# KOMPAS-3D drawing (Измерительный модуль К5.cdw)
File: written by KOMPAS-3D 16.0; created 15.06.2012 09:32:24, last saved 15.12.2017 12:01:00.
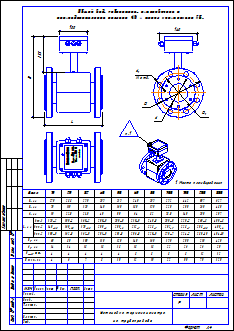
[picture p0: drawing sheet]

Sheet 1: A4, portrait

Title block, sheet 1: name: г. Москва, ул. Нежинская, д. 14, к.8 (кв. 1 и кв. 2); sheets: 31; sheet format: A4; stored path: W:\Users\chesnokov\Desktop\Новая папка\5 тр LTKR.cdw; cell 320: Р

Views: Вид 2, Вид 3, Вид 4, Вид 5
Referenced files in C:\Program Files (x86)\ASCON\KOMPAS-3D V16\Sys\: SPDS.lcs, EngSys.lcs, GRAPHIC.LHS
Referenced files: graphic.tdp
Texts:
  МО, Клинский район, д. Решетниково, ул. Центральная, д.14
  GOST Common
  Normal
  List Paragraph
  heading 3
  для схемы
  txt
  краны
  Фоновая заливка
  Т0-элементы
  N отв.
  Сделано в России
  Тmax= 150 C
  ИНТЕЛПРИБОР
  Общий вид, габаритные, установочные и
  присоединительные размеры ИМ с типом конструкции К5.
  Ду,мм
  Н, мм
  D, мм
  d, мм
  вар.1
  L, мм
  вар.2
  вар.3
  Масса, кг
  1. Место пломбирования
  Размеры, параметризация
  сит. план
  подача ГВС
  обратка ГВС
  хвс
  обратка
  POLYLINE_STYLE_0.25_RGB_0_0_0
  стены
  Основная (не является границей для штриховки)
  POLYLINE_STYLE_0.18_RGB_0_0_0
  ХВС
  зеленая
  Красная тонкая
  арматура
  Подача
  Скрытая линия
  Ось Z
  Ось Y
  Ось X
  Образующая трубопровода (проектируемого)
  Трубопровод толщиной 0.6мм (одна линия)
  Трубопровод толщиной 1.2мм (одна линия)
  Трубопровод толщиной 1.0мм (одна линия)
  Трубопровод толщиной 0.8мм (одна линия)
  Трубопровод существующий (одна линия)
  Трубопровод невидимый (одна линия)
  Трубопровод демонтируемый (одна линия)
  Осевая трубопровода
  Осевая трубопровода (демонтируемого)
  Образующая трубопровода (существующего)
  Образующая трубопровода (невидимого)
  Изолированный трубопровод проектируемый (одна линия)
  Изолированный трубопровод существующий (одна линия)
  Образующая изоляции
  Изоляция
  Изолированный трубопровод невидимый (одна линия)
  Штрих пвс 075
  штрих пвс 2,5
  существующее оборудование
  Существующее оборудование
  K5LT_BASIC_RGB_0_0_255_THICK_0.53
  POLYLINE_STYLE_1.51_RGB_0_0_255
  POLYLINE_STYLE_0.50_RGB_128_128_128
  K5LT_AXLED_RGB_255_128_0_SC_1_THICK_0.18
  ACAD_ISO04W100_RGB_0_0_0_SC_1_THICK_0.18
  тонкая черная
  пломбировка
  Провода
  синий штрих
  Стили документа
  G2co
  расход вторичной воды объемный
  расход вторичной воды объемный при 70гр
  Gco
  расход теплоносителя массовый
  расход теплоносит объемн подающ
  расход теплоносит объемн обр
  Лапир
  Ghvs
  Im1
  Im2
  Im3
  Im4
  Im5
  Khvs
  норматив ХВС
  число подъездов
  число этажей
  Nkv
  число квартир
  тепловая нагрузка на отопление
  сумма Q
  Qgvs
  тепловая нагрузка ГВС
  тепловая нагрузка на циркуляцию ГВС
  иммитовставка или под манометр
  ro1
  ro2
  ro3
  ro4
  верх предел темп граф
  нижн предел темп граф
  темп подачи ГВС
  темп обр ГВС
  темр хол воды
  vzdh
  Kchn
  Ktp
  Knp
  beta
  tnv
  Vклап
  KLP
  RPD
  RDS
  PUMP
  ro5
  Переход К-76 x 3-38 x 2-09Г2С ГОСТ 17378-2001
  Переход ГОСТ 17378-2001
  Переход
  ГОСТ
  Сталь 09Г2С ГОСТ 19281-89
  Переход К-76 x 3-45 x 2,5-09Г2С ГОСТ 17378-2001
  Переход К-57 x 3-38 x 2-09Г2С ГОСТ 17378-2001
  Переход К-57 x 3-32 x 2-09Г2С ГОСТ 17378-2001
  Втулка 20x50
  Переход К-108 x 4-57 x 3-09Г2С ГОСТ 17378-2001
  Переход К-45 x 2,5-32 x 2-09Г2С ГОСТ 17378-2001
  Переход К-89 x 3,5-45 x 2,5-09Г2С ГОСТ 17378-2001
  Переход К-133 x 5-108 x 4-09Г2С ГОСТ 17378-2001
  Переход К-159 x 4,5-89 x 3,5-09Г2С ГОСТ 17378-2001
  Переход К-45 x 2,5-38 x 2-09Г2С ГОСТ 17378-2001
  Фланец 1-32-1 Ст3сп ГОСТ 12820-80
  Фланцы
  Фланец
  квадратный
  Ст3сп
  Ст3сп ГОСТ 380-2005
  Переход К-57 x 3-45 x 2,5-09Г2С ГОСТ 17378-2001
  Переход К-76 x 3-57 x 3-09Г2С ГОСТ 17378-2001
  Фланец 1-50-16 Ст3сп ГОСТ 12821-80
  Переход К-89 x 3,5-76 x 3,5-09Г2С ГОСТ 17378-2001
  Переход К-108 x 4-89 x 3,5-09Г2С ГОСТ 17378-2001
  Тройник 159 x 4,5-09Г2С ГОСТ 17376-2001
  Тройники ГОСТ 17376-2001
  Тройник
  Отвод 90-159 x 4-09Г2С ГОСТ 17375-2001
  Отвод ГОСТ 17375-2001
  Отвод
  Переход К-108 x 4-76 x 3,5-09Г2С ГОСТ 17378-2001
  Переход К-159 x 4,5-108 x 4-09Г2С ГОСТ 17378-2001
  Переход К-133 x 5-76 x 3,5-09Г2С ГОСТ 17378-2001
  Переход К-133 x 4-89 x 3,5-09Г2С ГОСТ 17378-2001
  Переход К-1-42,4 x 2,6-21,3 x 2-TS10 ГОСТ 17378-2001
  TS10
  Сталь TS10 ИСО 2604/2-75
  Фланец 1-20-16 Ст3сп ГОСТ 12820-80
  Лит-Масса-Масштаб
  Материал-Предприятие
  Title Specification
  Body Specification ( left align )
  Body Specificaton ( centered )
  Поз.
  Кол.
  Приме-
  чание
  Таблица спецификации
  Засыпка
  Штрих3
  Штрих2
  Штрих1
  Песок
  Штр0.5пр7
  Штр0.5пр12
  Штр0.3пр10
  Штр1.4пр21.21
  Штр1пр15
  Штр2.12пр35
  Штр1.5пр25
  Штр2.82пр42.42
  Штр2пр30
  SACNCR_ISO 1
  Электрощитовая
  Пр-1
  Ок-1
  вапвыапвы
  Обозначение стандарта
  Типоразмер
  Разраб.
  Пров.
  Т.контр.
  Н.контр.
  Утв.
  Установка термоманометра
  на трубопроводе
  Рабочие чертежи основного комплекта. ГОСТ Р 21.1101-2009 Ф3
  Стадия
  Лист
  Листов
  Изм.
  Кол.уч.
  №док.
  Подп.
  Дата
  Изменение
  Номер документа
  Подпись
  Наименование объекта строительства, в состав которого входит здание, наим. микр
  Наименование здания (сооружения)
  Порядковый номер листа
  Количество листов в документе
  Наименование изображения
  Индекс предприятия, выпускающего документ
  Инв. № подл.
  Подп. и дата
  Взам. инв. №
  Инвентарный номер подлинника
  Подпись принявшего подлинник на хранение
  Инвентарный номер подлинника, взамен которого выпущен данный подлинник
  Согласовано
  Формат листа
  Согласование
  03 Рабочие чертежи основного комплекта. ГОСТ Р 21.1101-2009 Ф3
Dimensions and other numbers on the sheet: 0; 140; 100; 15; 25; 32; 40; 50; 65; 80; 150; 200; 300; 275; 95; 135 3; 140 -1,5; 155 5; 14; 4; 288; 115; 23,5; 155 3; 160 -1,5; 162 5; 85; 6; 295; 135; 31,5; 160 3; 190 -1,5; 18; 7; 309; 145; 200 5; 200 -2; 201 5; 110; 8; 319; 160; 205 5; 125; 10; 340; 180; 64; 210 5; 213 -3; 206 5; 12; 359; 392; 442; 507; 627; 195; 230; 360; 485; 82; 98,5; 307; 240 5; 238 -3; 230 5; 250 5; 252 -3; 270 7; 320 7; 328 -3; 324 7; 360 8; 258 -3,5; 380 10; 450 8; 450 -4; 454 10; 190; 250; 310; 430; 22; 26; 30; 70; 133; 1; 09Г2С; 2; 3; 16; 17; 19; 20; 21; 23; 24; 31; 33; 34; 52; 66; 67; 69; 71; 72; 73; 74; 75; 5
